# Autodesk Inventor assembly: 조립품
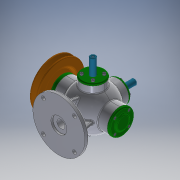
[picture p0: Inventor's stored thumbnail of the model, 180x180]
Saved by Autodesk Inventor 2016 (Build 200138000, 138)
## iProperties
Created: 2019-11
Part Number: 조립품
Material: 일반
Document SubType Name: Assembly
Designer: user
Mass: 3778.22 g
Surface Area: 2410.89 cm^2
Volume: 904.615 cm^3
Density: 4.17661 g/cm^3
Author: user
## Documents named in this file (17)
- C:\Users\user\Desktop\391120V1002\조립품.iam
- C:\Users\user\Desktop\391120V1002\V-벨트풀리.ipt
- C:\Users\user\Desktop\391120V1002\너트 M8x1.ipt
- C:\Users\user\Desktop\391120V1002\뒤커버.ipt
- C:\Users\user\Desktop\391120V1002\베어링 6202.ipt
- C:\Users\user\Desktop\391120V1002\본체.ipt
- C:\Users\user\Desktop\391120V1002\본체커버.ipt
- C:\Users\user\Desktop\391120V1002\볼트 M4.ipt
- C:\Users\user\Desktop\391120V1002\스프링1.ipt
- C:\Users\user\Desktop\391120V1002\스프링2.ipt
- C:\Users\user\Desktop\391120V1002\슬라이드 커버.ipt
- C:\Users\user\Desktop\391120V1002\슬라이드.ipt
- C:\Users\user\Desktop\391120V1002\앞커버.ipt
- C:\Users\user\Desktop\391120V1002\오일 실.ipt
- C:\Users\user\Desktop\391120V1002\와셔 8x17.ipt
- C:\Users\user\Desktop\391120V1002\축.ipt
- C:\Users\user\Desktop\391120V1002\키 4x4.ipt
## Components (1 placed, 1 different names)
1. V-벨트풀리:1
